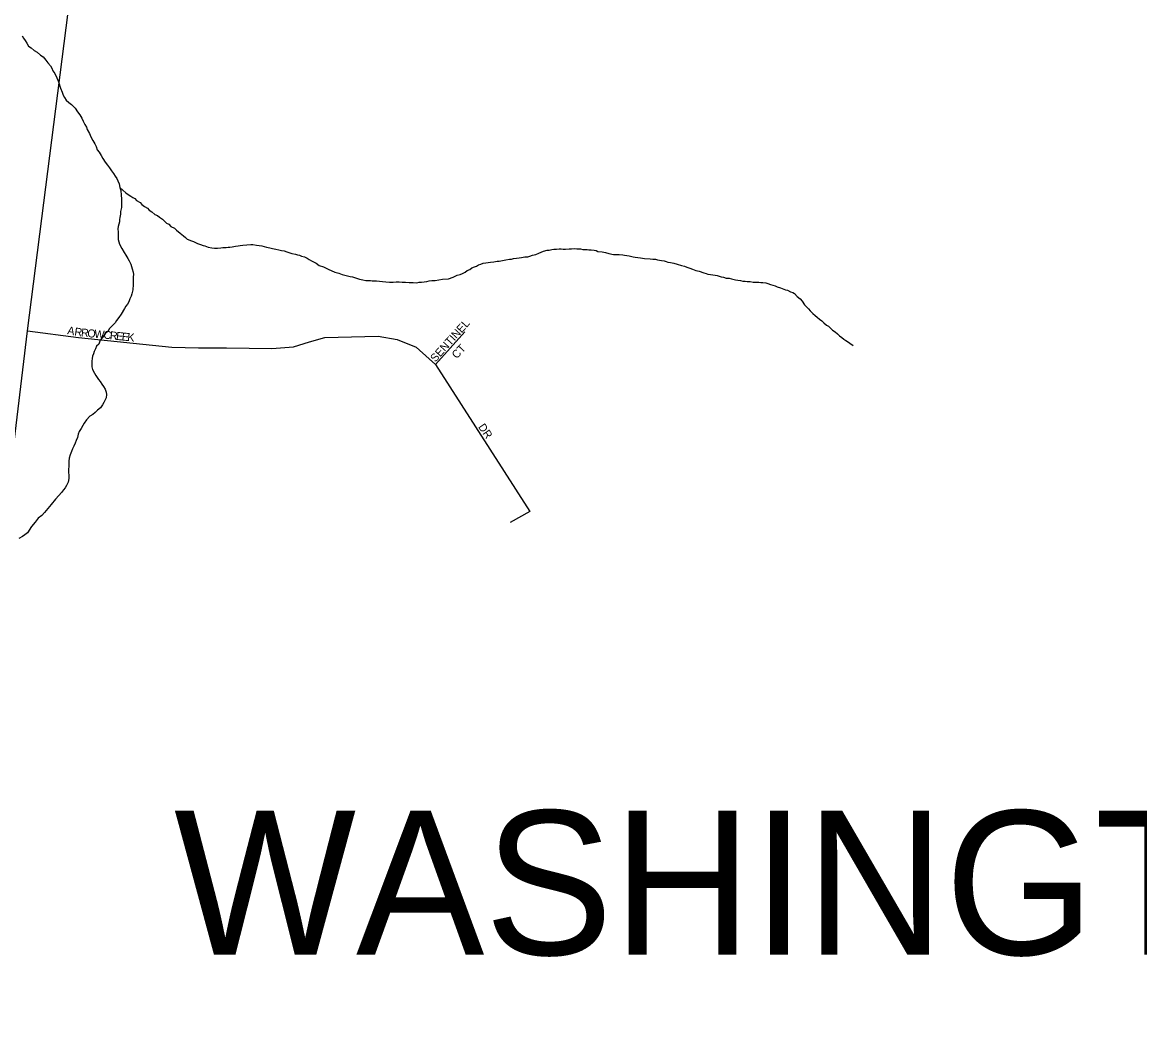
# Model space of a CAD drawing. Extents: x 0.4 to 34.4, y -2.1 to 19.9.
# Drawn here: x 7.097 to 8.419, y 13.456 to 14.658 of the extents above; entities that cross this region are included whole.
import ezdxf

# ---------------------------------------------------------------- set-up
doc = ezdxf.new("R2010")
doc.units = 0
for name, color, linetype in [('GM_X_Minor_River', 7, 'Continuous'), ('GM_X_Township_Road', 7, 'Continuous'), ('GM_X_Township_Subdivision', 7, 'Continuous'), ('GM_X_Township_Subdivision_Text', 7, 'Continuous'), ('GM_X_Township_Text', 7, 'Continuous')]:
    doc.layers.add(name, color=color, linetype=linetype)

msp = doc.modelspace()

# ---------------------------------------------------------------- linework, layer by layer
at = {"layer": 'GM_X_Minor_River'}
for points in [[(7.0966, 14.6418), (7.0984, 14.6391), (7.1003, 14.6364), (7.1021, 14.633), (7.1043, 14.6295), (7.1073, 14.6275), (7.1111, 14.6244), (7.1145, 14.6225), (7.1186, 14.619), (7.1216, 14.617), (7.1249, 14.6131), (7.1272, 14.61), (7.1301, 14.6062), (7.132, 14.6035), (7.133, 14.6004), (7.1353, 14.5973), (7.1378, 14.592), (7.1396, 14.5874), (7.1421, 14.5797), (7.1439, 14.5751), (7.1454, 14.5717), (7.1468, 14.5686), (7.149, 14.5655), (7.152, 14.5628), (7.155, 14.5604), (7.1595, 14.5562), (7.1621, 14.5519), (7.165, 14.5481), (7.1672, 14.5442), (7.1691, 14.5408), (7.1709, 14.5369), (7.1727, 14.5335), (7.1738, 14.5308), (7.1764, 14.5262), (7.1782, 14.5223), (7.1804, 14.5181), (7.1826, 14.5139), (7.1844, 14.5108), (7.1855, 14.507), (7.1877, 14.5043), (7.1903, 14.5), (7.1921, 14.4966), (7.1951, 14.4923), (7.1976, 14.4889), (7.1999, 14.4854), (7.2024, 14.4819), (7.2047, 14.4789), (7.2069, 14.4758), (7.2087, 14.4731), (7.2098, 14.47), (7.2116, 14.4665), (7.2123, 14.4623), (7.2134, 14.4589), (7.214, 14.4532), (7.2143, 14.449), (7.2142, 14.4444), (7.2141, 14.4414), (7.2141, 14.4387), (7.2132, 14.4338), (7.2131, 14.4308), (7.2123, 14.427), (7.2118, 14.4243), (7.2118, 14.4216), (7.2105, 14.4163), (7.2101, 14.4133), (7.2104, 14.4095), (7.2103, 14.4049), (7.2105, 14.4007), (7.2112, 14.3981), (7.2119, 14.3954)], [(7.2123, 14.4623), (7.2194, 14.4558), (7.222, 14.4542), (7.2254, 14.4522), (7.2277, 14.4503), (7.2299, 14.4491), (7.2322, 14.4468), (7.2363, 14.4444), (7.2385, 14.4421), (7.2415, 14.4397), (7.2449, 14.4378), (7.2472, 14.4355), (7.2502, 14.4335), (7.2539, 14.4304), (7.2569, 14.4292), (7.2592, 14.4272), (7.2626, 14.4249), (7.2648, 14.423), (7.2674, 14.4202), (7.2704, 14.419), (7.2727, 14.4163), (7.2768, 14.414), (7.2794, 14.412), (7.2835, 14.4081), (7.2877, 14.405), (7.2899, 14.4031), (7.2921, 14.4011), (7.2971, 14.3991), (7.2993, 14.3983), (7.3042, 14.396), (7.3076, 14.3948), (7.3107, 14.3936), (7.3129, 14.3931), (7.3167, 14.3919), (7.3213, 14.3911), (7.3243, 14.3907), (7.3277, 14.3906), (7.3319, 14.3909), (7.3342, 14.3912), (7.3381, 14.3915), (7.3404, 14.3919), (7.3426, 14.3918), (7.3453, 14.3922), (7.3492, 14.3929), (7.3522, 14.3932), (7.3545, 14.3935), (7.358, 14.3942), (7.3625, 14.3945), (7.3671, 14.3948), (7.3698, 14.3948), (7.374, 14.3939), (7.377, 14.3935), (7.3804, 14.3931), (7.3831, 14.3926), (7.3857, 14.3918), (7.3899, 14.391), (7.3929, 14.3902), (7.3967, 14.3893), (7.4005, 14.3885), (7.4036, 14.3877), (7.4066, 14.3872), (7.41, 14.386), (7.4157, 14.3844), (7.4202, 14.3836), (7.4225, 14.3828), (7.4248, 14.3823), (7.4271, 14.3812), (7.4308, 14.3803), (7.4339, 14.3788), (7.4361, 14.3772), (7.4391, 14.3756), (7.4414, 14.3744), (7.4444, 14.3728), (7.4482, 14.3701), (7.4531, 14.3685), (7.4557, 14.3673), (7.4595, 14.3653), (7.4625, 14.3641), (7.4667, 14.3622), (7.4712, 14.3609), (7.4754, 14.3593), (7.4799, 14.3581), (7.4848, 14.3569), (7.4875, 14.3565), (7.4924, 14.3552), (7.4958, 14.354), (7.4996, 14.3532), (7.5034, 14.3524), (7.5065, 14.3523), (7.5088, 14.3523), (7.511, 14.3518), (7.5137, 14.3518), (7.516, 14.3517), (7.5194, 14.3513), (7.5232, 14.3512), (7.527, 14.3508), (7.5312, 14.3503), (7.5358, 14.3502), (7.5392, 14.3506), (7.5427, 14.3505), (7.5465, 14.3504)], [(7.2119, 14.3954), (7.2145, 14.39), (7.2174, 14.3854), (7.2193, 14.3823), (7.2219, 14.3781), (7.2233, 14.3754), (7.2255, 14.3715), (7.2262, 14.3689), (7.2269, 14.3662), (7.228, 14.362), (7.2283, 14.3593), (7.2282, 14.3567), (7.2282, 14.3536), (7.228, 14.3475), (7.2275, 14.3411), (7.2266, 14.3365), (7.2258, 14.3339), (7.2242, 14.3305), (7.223, 14.3271), (7.2214, 14.3244), (7.2194, 14.3218), (7.2179, 14.3192), (7.2139, 14.3124), (7.2111, 14.3086), (7.2084, 14.3049), (7.2068, 14.3022), (7.2033, 14.2985), (7.2002, 14.2955), (7.1982, 14.2918), (7.1955, 14.2899), (7.1919, 14.285), (7.1892, 14.2816), (7.1876, 14.2771), (7.1848, 14.2745), (7.1836, 14.2715), (7.182, 14.2681), (7.1812, 14.2654), (7.18, 14.2628), (7.1795, 14.2598), (7.1791, 14.2567), (7.179, 14.2541), (7.1793, 14.2502), (7.18, 14.2468), (7.1822, 14.2426), (7.1841, 14.2399), (7.187, 14.2353), (7.1889, 14.2326), (7.1911, 14.2295), (7.1929, 14.2268), (7.1948, 14.2237), (7.1962, 14.2203), (7.1965, 14.2172), (7.196, 14.2134), (7.1933, 14.2081), (7.1917, 14.2051), (7.1893, 14.2017), (7.1858, 14.1988), (7.1831, 14.1961), (7.1804, 14.1939), (7.1769, 14.1917), (7.173, 14.1876), (7.1702, 14.1834), (7.1686, 14.1808), (7.1666, 14.177), (7.1643, 14.1737), (7.1631, 14.1706), (7.1622, 14.1665), (7.1606, 14.1631), (7.1594, 14.1597), (7.1578, 14.1563), (7.1562, 14.1529), (7.155, 14.1499), (7.1537, 14.1461), (7.1525, 14.1419), (7.152, 14.1385), (7.1519, 14.1324), (7.1514, 14.1286), (7.1517, 14.1252), (7.1521, 14.1218), (7.152, 14.1179), (7.1511, 14.1138), (7.1491, 14.1096), (7.1475, 14.107), (7.1456, 14.1044), (7.1432, 14.1014), (7.1401, 14.098), (7.1362, 14.0935), (7.1311, 14.0871), (7.1272, 14.0826), (7.1232, 14.0778), (7.1201, 14.0744), (7.1158, 14.0711), (7.1123, 14.0665), (7.108, 14.0613), (7.1029, 14.0538), (7.1001, 14.0512), (7.097, 14.0493), (7.0928, 14.0471)], [(7.5465, 14.3504), (7.5503, 14.3504), (7.5545, 14.3499), (7.5594, 14.3498), (7.5636, 14.3497), (7.5663, 14.3501), (7.569, 14.3504), (7.5724, 14.3507), (7.5755, 14.351), (7.5781, 14.3517), (7.5816, 14.3521), (7.5854, 14.3524), (7.5896, 14.3531), (7.5942, 14.3537), (7.6011, 14.3544), (7.6065, 14.3562), (7.6115, 14.3587), (7.6149, 14.3594), (7.6176, 14.3605), (7.6207, 14.362), (7.6234, 14.3642), (7.6265, 14.3653), (7.6288, 14.3672), (7.6319, 14.3683), (7.6342, 14.3694), (7.6365, 14.3708), (7.6392, 14.3716), (7.6423, 14.3726), (7.6453, 14.3733), (7.648, 14.3737), (7.6507, 14.374), (7.6549, 14.3743), (7.6587, 14.375), (7.661, 14.3753), (7.6649, 14.376), (7.6691, 14.3767), (7.6733, 14.3774), (7.6756, 14.3777), (7.6779, 14.3781), (7.6817, 14.3788), (7.6847, 14.3791), (7.6874, 14.3794), (7.6916, 14.3801), (7.6951, 14.3804), (7.6974, 14.3811), (7.7004, 14.3822), (7.7043, 14.3829), (7.7081, 14.3847), (7.7108, 14.3858), (7.7135, 14.3869), (7.7177, 14.388), (7.7204, 14.3883), (7.7235, 14.389), (7.7258, 14.3894), (7.7288, 14.3893), (7.7319, 14.3896), (7.7345, 14.3896), (7.7368, 14.3895), (7.7395, 14.3895), (7.7437, 14.3898), (7.7468, 14.3897), (7.7506, 14.3901), (7.7528, 14.3896), (7.7551, 14.3896), (7.7574, 14.3896), (7.7601, 14.3891), (7.7624, 14.3891), (7.765, 14.389), (7.7673, 14.3886), (7.77, 14.3886), (7.7734, 14.3881), (7.7757, 14.3877), (7.7779, 14.3865), (7.7829, 14.386), (7.7867, 14.3852), (7.7909, 14.3844), (7.7962, 14.3831), (7.803, 14.383), (7.8072, 14.3826), (7.8095, 14.3821), (7.8122, 14.3817), (7.8148, 14.3813), (7.8194, 14.3804), (7.822, 14.38), (7.8251, 14.3796), (7.8281, 14.3791), (7.8308, 14.3787), (7.833, 14.3783), (7.8399, 14.3778), (7.8429, 14.3777), (7.846, 14.3777), (7.8483, 14.3768), (7.8509, 14.3764), (7.8532, 14.376), (7.8562, 14.3756), (7.8585, 14.3748), (7.8608, 14.374), (7.8638, 14.3735), (7.8676, 14.3727), (7.8718, 14.3715), (7.8767, 14.3702)], [(7.8767, 14.3702), (7.8805, 14.3694), (7.8831, 14.3682), (7.8866, 14.367), (7.8896, 14.3658), (7.8937, 14.3642), (7.8975, 14.3634), (7.9032, 14.3614), (7.9059, 14.3606), (7.9081, 14.3598), (7.9112, 14.3593), (7.9138, 14.3589), (7.9165, 14.3585), (7.9191, 14.358), (7.9214, 14.3572), (7.9237, 14.3568), (7.9263, 14.3564), (7.9298, 14.3552), (7.9332, 14.3551), (7.9358, 14.3543), (7.9408, 14.3531), (7.9434, 14.3527), (7.9465, 14.3522), (7.9495, 14.3514), (7.9522, 14.3513), (7.9544, 14.3509), (7.9579, 14.3509), (7.9617, 14.3504), (7.9651, 14.3503), (7.9682, 14.3503), (7.9708, 14.3499), (7.9731, 14.3498), (7.9765, 14.3494), (7.9788, 14.3486), (7.9822, 14.3474), (7.9875, 14.3458), (7.9898, 14.3449), (7.9939, 14.3434), (7.9977, 14.3421), (8, 14.3413), (8.0023, 14.3409), (8.0056, 14.3389), (8.0083, 14.3381), (8.0106, 14.337), (8.0135, 14.3335), (8.0173, 14.3307), (8.0195, 14.3277), (8.0221, 14.3234), (8.0247, 14.3211), (8.0269, 14.3188), (8.0288, 14.3165), (8.0321, 14.3133), (8.0351, 14.311), (8.0374, 14.3087), (8.04, 14.3064), (8.0426, 14.3044), (8.0452, 14.3021), (8.0482, 14.2994), (8.0505, 14.2982), (8.0527, 14.2962), (8.0553, 14.2935), (8.0587, 14.2916), (8.0613, 14.2892), (8.0636, 14.2869), (8.0666, 14.2849), (8.0688, 14.283), (8.0711, 14.2814), (8.0733, 14.2799), (8.076, 14.2783), (8.0797, 14.2752)]]:
    msp.add_lwpolyline(points, dxfattribs=at)
at = {"layer": 'GM_X_Township_Road'}
msp.add_lwpolyline([(6.0486, 13.0593), (6.2023, 13.1806), (6.9275, 13.7533), (6.9437, 13.7644), (6.9532, 13.768), (7.0189, 13.7683), (7.0311, 13.7726), (7.0415, 13.7819), (7.1029, 14.2928), (7.1535, 14.6887)], dxfattribs=at)
at = {"layer": 'GM_X_Township_Subdivision'}
for points in [[(7.1029, 14.2928), (7.1635, 14.285), (7.274, 14.2733), (7.3052, 14.2726), (7.3384, 14.2726), (7.3923, 14.272), (7.4177, 14.2739), (7.4365, 14.2798), (7.4547, 14.285), (7.5179, 14.2864), (7.5405, 14.2825), (7.5627, 14.2733), (7.5782, 14.2597), (7.5858, 14.2527), (7.6975, 14.0789), (7.674, 14.0659)], [(7.5858, 14.2527), (7.6205, 14.2916)]]:
    msp.add_lwpolyline(points, dxfattribs=at)

# ---------------------------------------------------------------- texts
at = {"layer": 'GM_X_Township_Subdivision_Text'}
for s, rotation, p in [('SENTINEL', 48.0757, (7.5856, 14.255)), ('A', 350.0921, (7.1497, 14.2889)), ('R', 351.3844, (7.1581, 14.2874)), ('R', 353.9671, (7.166, 14.2862)), ('O', 354.3497, (7.1735, 14.2854)), ('W', 354.3574, (7.1818, 14.2846)), ('C', 354.3736, (7.1926, 14.2836)), ('R', 354.3571, (7.2001, 14.2828)), ('E', 354.3499, (7.2075, 14.2821)), ('E', 354.3628, (7.2142, 14.2814)), ('K', 354.3525, (7.2208, 14.2808)), ('CT', 47.2983, (7.6109, 14.259)), ('DR', 304.5143, (7.6358, 14.179))]:
    msp.add_text(s, height=0.00947, rotation=rotation, dxfattribs=at).set_placement(p)
at = {"layer": 'GM_X_Township_Text'}
msp.add_text('WASHINGTON', height=0.17045, rotation=0, dxfattribs=at).set_placement((7.2765, 13.5544))

doc.saveas('drawing.dxf')
